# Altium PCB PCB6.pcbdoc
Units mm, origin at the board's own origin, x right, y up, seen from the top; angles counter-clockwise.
Board outline 112.7 x 112.94 mm, 2 copper layers (Top Layer, Bottom Layer); 46 components, 40 nets, 167 pads, 45 vias.
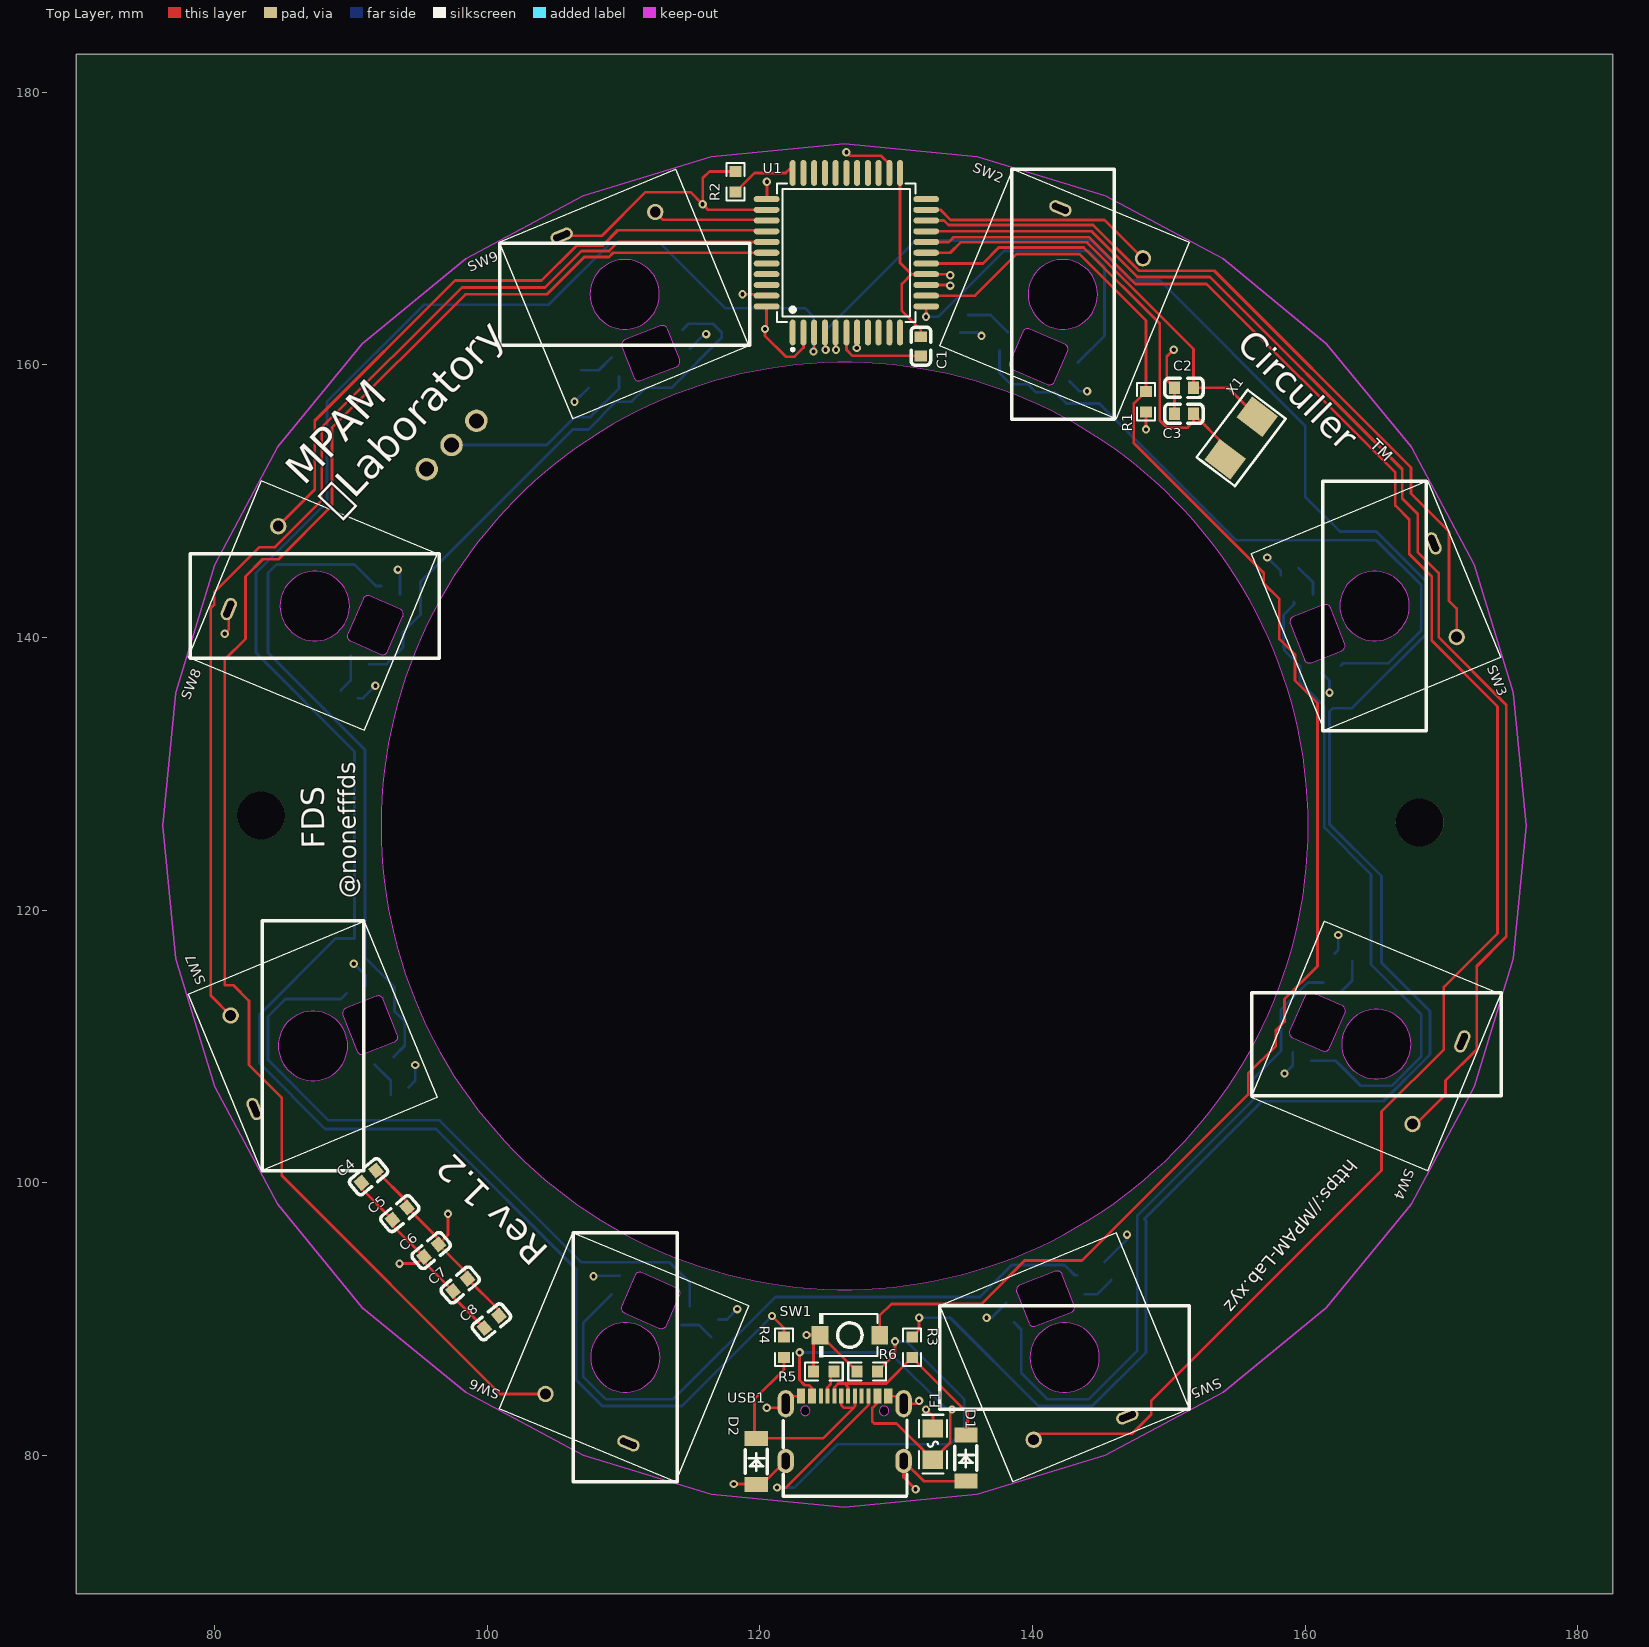
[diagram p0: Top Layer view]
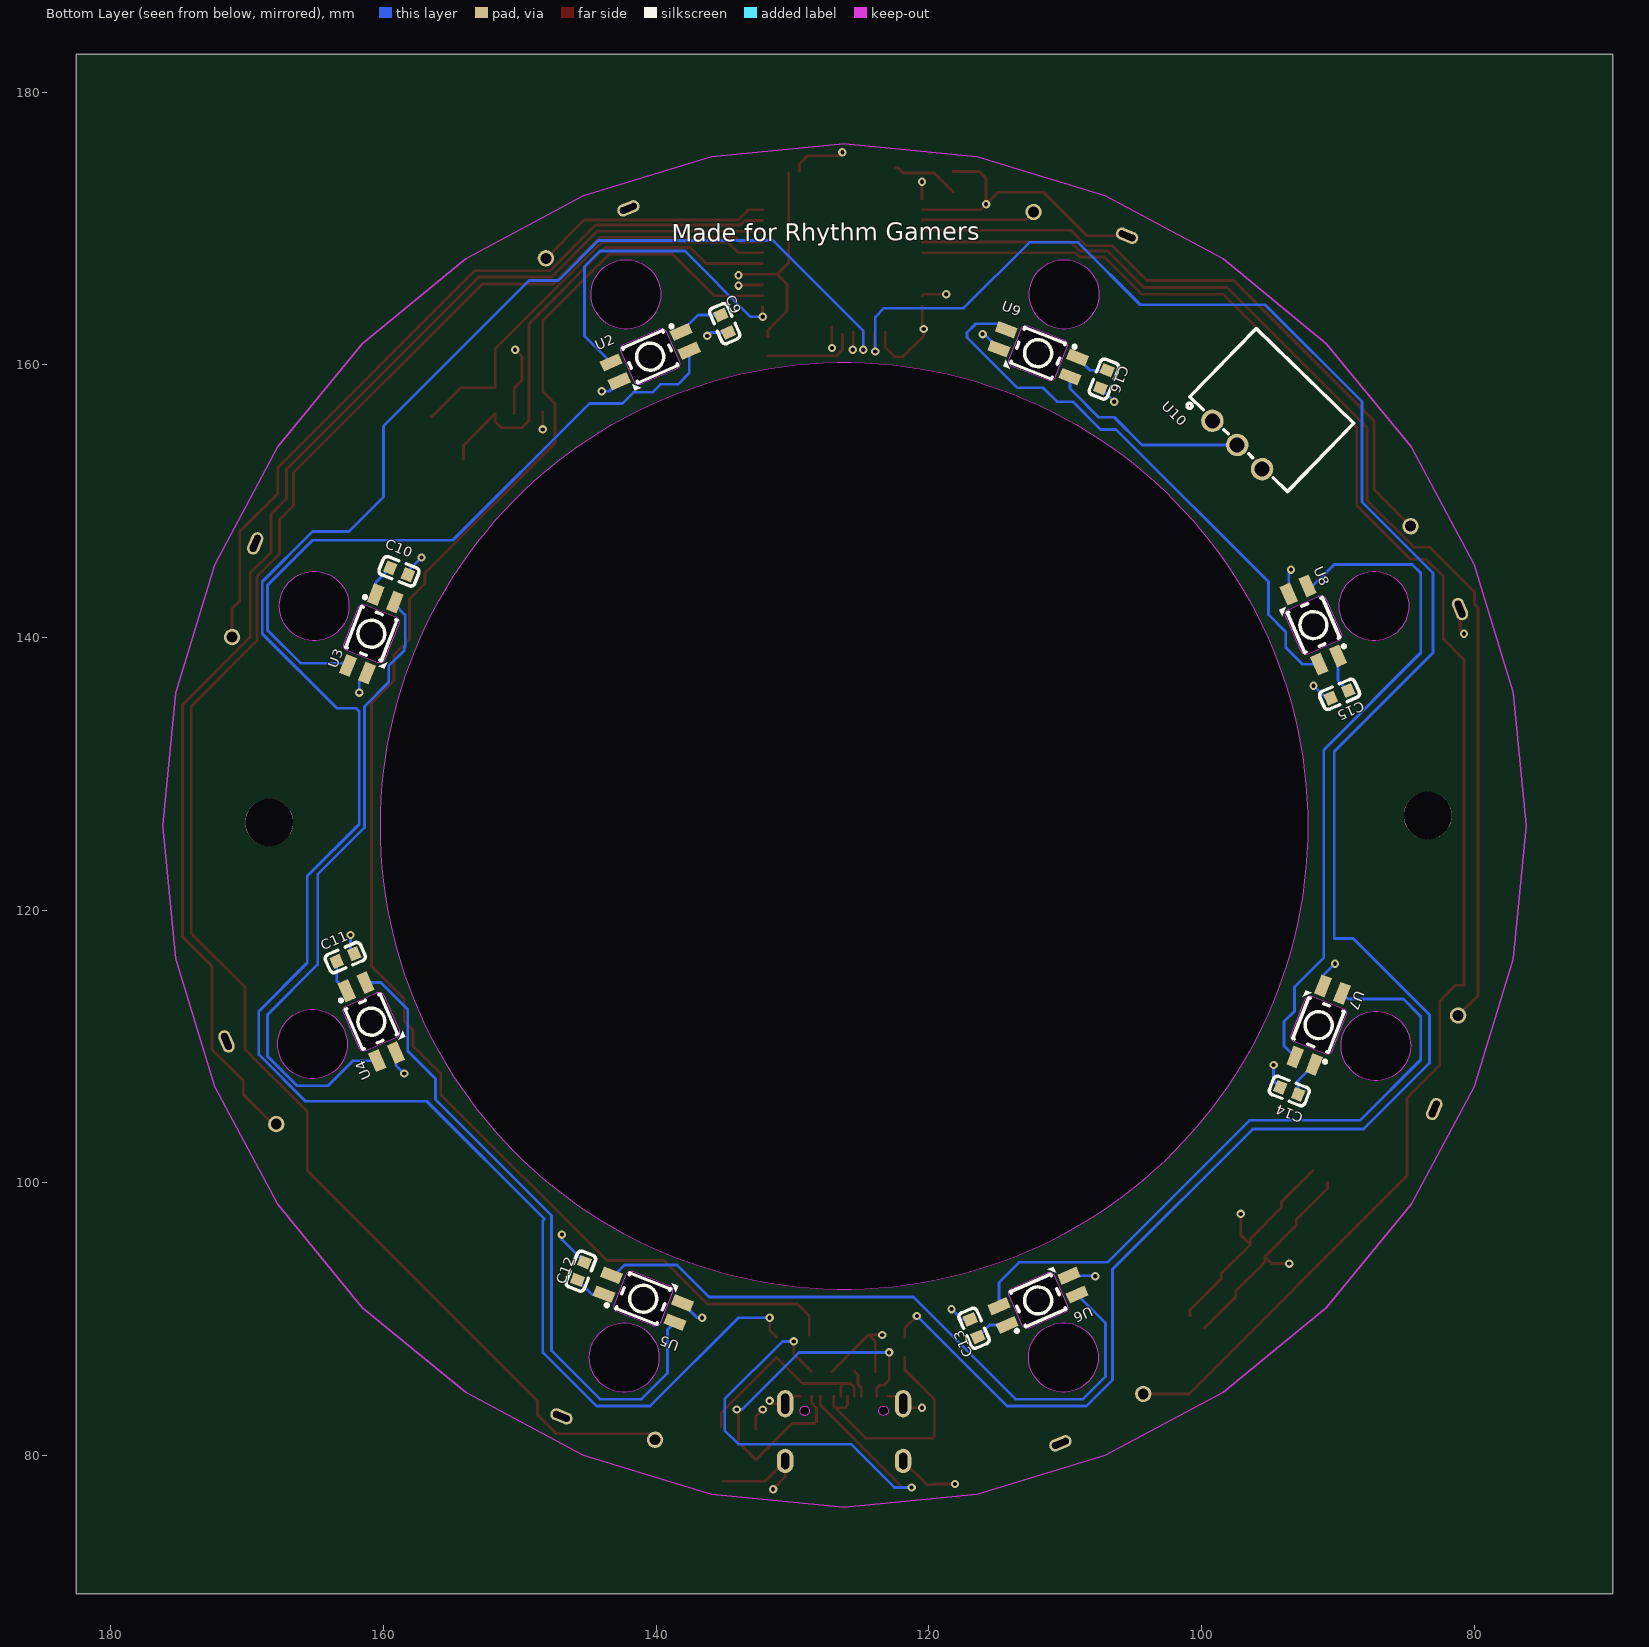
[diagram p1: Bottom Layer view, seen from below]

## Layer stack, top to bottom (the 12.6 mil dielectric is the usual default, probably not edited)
Top Layer: signal copper (thickness not stored)
Dielectric: dielectric 0.32, FR-4, Dk 4.8
Bottom Layer: signal copper (thickness not stored)

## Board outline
182.55,69.85 69.85,69.85 69.85,182.785 182.55,182.785
cut-out: 160.219,126.175 ccw(c126.219,126.175) 92.219,126.175 ccw(c126.219,126.175)

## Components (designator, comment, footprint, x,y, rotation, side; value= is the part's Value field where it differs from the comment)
C1 "CL10A105KB8NNNC" C0603 131.807,161.354 r270 top
C2 "CL10C220JB8NNNC" C0603 151.111,158.306 r0 top
C3 "CL10C220JB8NNNC" C0603 151.111,156.401 r0 top
C4 "CC0603KRX7R9BB104" C0603 91.309,100.454 r40.26 top
C5 "CC0603KRX7R9BB104" C0603 93.603,97.745 r40.26 top
C6 "CC0603KRX7R9BB104" C0603 95.897,95.037 r40.26 top
C7 "CC0603KRX7R9BB104" C0603 98.031,92.517 r40.26 top
C8 "CL10B474KA8NNNC" C0603 100.325,89.809 r40.26 top
C9 "CC0603KRX7R9BB104" C0603 134.982,163.005 r246.46 bottom
C10 "CC0603KRX7R9BB104" C0603 158.858,144.844 r201.46 bottom
C11 "CC0603KRX7R9BB104" C0603 162.795,116.523 r156.38 bottom
C12 "CC0603KRX7R9BB104" C0603 145.523,93.536 r111.38 bottom
C13 "CC0603KRX7R9BB104" C0603 116.694,89.345 r66.46 bottom
C14 "CC0603KRX7R9BB104" C0603 93.58,106.744 r21.46 bottom
C15 "CC0603KRX7R9BB104" C0603 89.897,135.827 r336.38 bottom
C16 "CC0603KRX7R9BB104" C0603 107.169,158.941 r291.38 bottom
D1 "ZMM3V6" LL-34_L3.5-W1.5-RD 135.109,79.82 r270 top
D2 "ZMM3V6" LL-34_L3.5-W1.5-RD 119.742,79.566 r270 top
F1 "2.5A/32VFUSESMD0805" F0805 132.696,80.836 r270 top
R1 "0603WAF1002T5E" R0603 148.317,157.29 r90 top
R2 "0603WAF1002T5E" R0603 118.218,173.419 r90 top
R3 "0603WAF220JT5E" R0603 131.172,87.948 r270 top
R4 "0603WAF220JT5E" R0603 121.774,87.948 r270 top
R5 "0603WAF5101T5E" R0603 124.695,86.17 r0 top
R6 "0603WAF5101T5E" R0603 127.87,86.17 r0 top
SW1 "TS-1088-AR02016" SW-SMD_L3.9-W3.0-P4.45 126.6,88.837 r180 top
SW2 "佳达隆矮轴_焊接" 佳达隆矮轴焊接#1 142.221,165.164 r337.31 top
SW3 "佳达隆矮轴_焊接" 佳达隆矮轴焊接#2 165.081,142.304 r292.39 top
SW4 "佳达隆矮轴_焊接" 佳达隆矮轴焊接#3 165.208,110.173 r247.48 top
SW5 "佳达隆矮轴_焊接" 佳达隆矮轴焊接#4 142.348,87.186 r202.51 top
SW6 "佳达隆矮轴_焊接" 佳达隆矮轴焊接#1 110.136,87.203 r157.7 top
SW7 "佳达隆矮轴_焊接" 佳达隆矮轴焊接#2 87.23,110.046 r112.88 top
SW8 "佳达隆矮轴_焊接" 佳达隆矮轴焊接#2 87.357,142.304 r67.7 top
SW9 "佳达隆矮轴_焊接" 佳达隆矮轴焊接#1 110.09,165.164 r22.79 top
U1 "ATMEGA32U4-AU" QFP-44_L10.0-W10.0-P0.80-LS13.2-BL 126.346,168.212 r0 top
U2 "WS2812B-3528幻彩反贴" LED-SMD_L3.2-W2.8-TR 140.443,160.592 r156.46 bottom
U3 "WS2812B-3528幻彩反贴" LED-SMD_L3.2-W2.8-TR 160.89,140.272 r111.46 bottom
U4 "WS2812B-3528幻彩反贴" LED-SMD_L3.2-W2.8-TR 160.89,111.824 r66.38 bottom
U5 "WS2812B-3528幻彩反贴" LED-SMD_L3.2-W2.8-TR 140.951,91.504 r21.38 bottom
U6 "WS2812B-3528幻彩反贴" LED-SMD_L3.2-W2.8-TR 111.995,91.377 r336.46 bottom
U7 "WS2812B-3528幻彩反贴" LED-SMD_L3.2-W2.8-TR 91.421,111.57 r291.46 bottom
U8 "WS2812B-3528幻彩反贴" LED-SMD_L3.2-W2.8-TR 91.802,140.907 r246.38 bottom
U9 "WS2812B-3528幻彩反贴" LED-SMD_L3.2-W2.8-TR 111.995,160.846 r201.38 bottom
U10 "XH2.54-WI-3P" CONN-TH_XH2.54-WI-3P 97.39,154.115 r224.2 bottom
USB1 "TYPE-C 16PIN 2MD(073)" USB-C-SMD_TYPE-C-6PIN-2MD-073 126.219,81.979 r0 top
X1 "XSHEELNANF-16MHZ" OSC-SMD_2P-L5.0-W3.2 155.302,154.623 r52.91 top

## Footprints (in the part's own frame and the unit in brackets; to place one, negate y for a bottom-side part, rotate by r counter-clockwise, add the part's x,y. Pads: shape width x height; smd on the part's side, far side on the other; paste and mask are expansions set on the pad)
C0603 [mm]
  rect 0.8x0.9 smd: 1(-0.7,0) 2(0.7,0)
  silkscreen extent -1.41,-0.71 1.39,0.72
CONN-TH_XH2.54-WI-3P [mm]
  round 1.65 hole 1.1: 1(-2.54,0) 2(0,0) 3(2.54,0)
  silkscreen extent -4.96,-0.56 5.02,7.09
F0805 [mm]
  rect 1.335x1.5 smd: 1(-1.142,0) 2(1.142,0)
  silkscreen extent -2.16,-1.02 2.16,1.02
LED-SMD_L3.2-W2.8-TR [mm]
  rect 1.5x0.82 smd: 1(2.8,0.75) 2(2.8,-0.75) 3(-2.8,-0.75) 4(-2.8,0.75)
  Multi-Layer board cut-out: 1.8,-1.2 1.746,-1.4 1.6,-1.547 1.4,-1.6 1.4,-1.6 1.4,-1.6 -1.4,-1.6 -1.403,-1.6 -1.406,-1.6 -1.406,-1.6 -1.604,-1.545 -1.747,-1.398 -1.8,-1.2 -1.8,-1.2 -1.8,-1.2 -1.8,-1.2 -1.8,-1.2 -1.8,-1.2 -1.8,1.2 -1.746,1.4 -1.6,1.546 -1.4,1.6 -1.4,1.6 1.4,1.6 1.4,1.6 1.6,1.547 1.746,1.4 1.8,1.2 1.8,1.2
  Multi-Layer keep-out region: 1.8,-1.2 1.746,-1.4 1.6,-1.547 1.4,-1.6 1.4,-1.6 1.4,-1.6 -1.4,-1.6 -1.403,-1.6 -1.406,-1.6 -1.406,-1.6 -1.604,-1.545 -1.747,-1.398 -1.8,-1.2 -1.8,-1.2 -1.8,-1.2 -1.8,-1.2 -1.8,-1.2 -1.8,-1.2 -1.8,1.2 -1.746,1.4 -1.6,1.546 -1.4,1.6 -1.4,1.6 1.4,1.6 1.4,1.6 1.6,1.547 1.746,1.4 1.8,1.2 1.8,1.2
  silkscreen extent -2.03,-1.83 2.42,1.52
LL-34_L3.5-W1.5-RD [mm]
  rect 1.1x1.7 smd: 1(-1.7,0) 2(1.7,0)
  silkscreen extent -0.9,-0.8 0.9,0.8
OSC-SMD_2P-L5.0-W3.2 [mm]
  rect 1.9x2.4 smd: 1(-1.95,0) 2(1.95,0)
  silkscreen extent -3.1,-1.75 3.1,1.75
QFP-44_L10.0-W10.0-P0.80-LS13.2-BL [mil]
  oval 17.36x74.62 smd: 1(-155,-230.37) 2(-124,-230.37) 3(-93,-230.37) 4(-62,-230.37) 5(-31,-230.37) 6(0,-230.37) 7(31,-230.37) 8(62,-230.37) 9(93,-230.37) 10(124,-230.37) 11(155,-230.37) 23(155,230.37) 24(124,230.37) 25(93,230.37) 26(62,230.37) 27(31,230.37) 28(0,230.37) 29(-31,230.37) 30(-62,230.37) 31(-93,230.37) 32(-124,230.37) 33(-155,230.37)
  oval 74.62x17.36 smd: 12(230.37,-155) 13(230.37,-124) 14(230.37,-93) 15(230.37,-62) 16(230.37,-31) 17(230.37,0) 18(230.37,31) 19(230.37,62) 20(230.37,93) 21(230.37,124) 22(230.37,155) 34(-230.37,155) 35(-230.37,124) 36(-230.37,93) 37(-230.37,62) 38(-230.37,31) 39(-230.37,0) 40(-230.37,-31) 41(-230.37,-62) 42(-230.37,-93) 43(-230.37,-124) 44(-230.37,-155)
  silkscreen extent -200,-283 200,200
R0603 [mm]
  rect 0.806x0.864 smd: 1(-0.753,0) 2(0.753,0)
  silkscreen extent -1.39,-0.66 1.39,0.66
SW-SMD_L3.9-W3.0-P4.45 [mm]
  rect 1.23x1.36 smd: 1(-2.185,0) 2(2.185,0)
  silkscreen extent -2.03,-1.62 2.25,1.62
USB-C-SMD_TYPE-C-6PIN-2MD-073 [mm]
  rect 0.6x1.1 smd: 1(-3.2,2.375) 2(-2.4,2.375) 11(2.4,2.375) 12(3.2,2.375)
  rect 0.3x1.1 smd: 3(-1.75,2.375) 4(-1.25,2.375) 5(-0.75,2.375) 6(-0.25,2.375) 7(0.25,2.375) 8(0.75,2.375) 9(1.25,2.375) 10(1.75,2.375)
  oval 1.2x1.8 hole 0.6 slot 1.2 at 90 deg: 13(-4.325,-2.375) 14(4.325,-2.375)
  oval 1.2x2 hole 0.6 slot 1.5 at 90 deg: 13(-4.325,1.825) 14(4.325,1.825)
  Multi-Layer board cut-out: -2.54,1.305 -2.575,1.457 -2.672,1.579 -2.812,1.646 -2.968,1.646 -3.108,1.579 -3.205,1.457 -3.24,1.305 -3.24,1.305 -3.205,1.153 -3.108,1.031 -2.968,0.964 -2.812,0.964 -2.672,1.031 -2.575,1.153 -2.54,1.305
  Multi-Layer board cut-out: 3.24,1.305 3.205,1.457 3.108,1.579 2.968,1.646 2.812,1.646 2.672,1.579 2.575,1.457 2.54,1.305 2.54,1.305 2.575,1.153 2.672,1.031 2.812,0.964 2.968,0.964 3.108,1.031 3.205,1.153 3.24,1.305
  Multi-Layer keep-out region: -2.54,1.305 -2.575,1.457 -2.672,1.579 -2.812,1.646 -2.968,1.646 -3.108,1.579 -3.205,1.457 -3.24,1.305 -3.24,1.305 -3.205,1.153 -3.108,1.031 -2.968,0.964 -2.812,0.964 -2.672,1.031 -2.575,1.153 -2.54,1.305
  Multi-Layer keep-out region: 3.24,1.305 3.205,1.457 3.108,1.579 2.968,1.646 2.812,1.646 2.672,1.579 2.575,1.457 2.54,1.305 2.54,1.305 2.575,1.153 2.672,1.031 2.812,0.964 2.968,0.964 3.108,1.031 3.205,1.153 3.24,1.305
  silkscreen extent -4.5,-4.97 4.57,0.6
佳达隆矮轴焊接#1 [mm]
  oval 1.7x0.9 hole 0.5 slot 1.3 at 0 deg: 1(-2.6,5.75)
  round 1.2 hole 0.8: 2(4.4,4.7)
  Multi-Layer board cut-out: 2.353,0.984 1.693,1.907 0.698,2.453 -0.436,2.513 -1.483,2.075 -2.236,1.226 -2.546,0.134 -2.353,-0.984 -2.353,-0.984 -1.693,-1.907 -0.698,-2.453 0.436,-2.513 1.483,-2.075 2.236,-1.226 2.546,-0.134 2.353,0.984
  Multi-Layer keep-out region: 2.353,0.984 1.693,1.907 0.698,2.453 -0.436,2.513 -1.483,2.075 -2.236,1.226 -2.546,0.134 -2.353,-0.984 -2.353,-0.984 -1.693,-1.907 -0.698,-2.453 0.436,-2.513 1.483,-2.075 2.236,-1.226 2.546,-0.134 2.353,0.984
  silkscreen extent -7,-9.9 7,9.9
佳达隆矮轴焊接#2 [mm]
  oval 1.7x0.9 hole 0.5 slot 1.3 at 0 deg: 1(-2.6,5.75)
  round 1.2 hole 0.8: 2(4.4,4.7)
  Multi-Layer board cut-out: 0.971,2.358 -0.148,2.546 -1.238,2.229 -2.083,1.471 -2.515,0.422 -2.449,-0.711 -1.898,-1.703 -0.971,-2.358 -0.971,-2.358 0.148,-2.546 1.238,-2.229 2.083,-1.471 2.515,-0.422 2.449,0.711 1.898,1.703 0.971,2.358
  Multi-Layer keep-out region: 0.971,2.358 -0.148,2.546 -1.238,2.229 -2.083,1.471 -2.515,0.422 -2.449,-0.711 -1.898,-1.703 -0.971,-2.358 -0.971,-2.358 0.148,-2.546 1.238,-2.229 2.083,-1.471 2.515,-0.422 2.449,0.711 1.898,1.703 0.971,2.358
  silkscreen extent -9.9,-7 9.9,7
佳达隆矮轴焊接#3 [mm]
  oval 1.7x0.9 hole 0.5 slot 1.3 at 180 deg: 1(-2.6,5.75)
  round 1.2 hole 0.8: 2(4.4,4.7)
  Multi-Layer board cut-out: -0.977,2.356 -1.902,1.699 -2.451,0.705 -2.514,-0.428 -2.079,-1.476 -1.233,-2.232 -0.142,-2.546 0.977,-2.356 0.977,-2.356 1.902,-1.699 2.451,-0.705 2.514,0.428 2.079,1.476 1.233,2.232 0.142,2.546 -0.977,2.356
  Multi-Layer keep-out region: -0.977,2.356 -1.902,1.699 -2.451,0.705 -2.514,-0.428 -2.079,-1.476 -1.233,-2.232 -0.142,-2.546 0.977,-2.356 0.977,-2.356 1.902,-1.699 2.451,-0.705 2.514,0.428 2.079,1.476 1.233,2.232 0.142,2.546 -0.977,2.356
  silkscreen extent -7,-9.9 7,9.9
佳达隆矮轴焊接#4 [mm]
  oval 1.7x0.9 hole 0.5 slot 1.3 at 180 deg: 1(-2.6,5.75)
  round 1.2 hole 0.8: 2(4.4,4.7)
  Multi-Layer board cut-out: -2.356,0.976 -2.546,-0.142 -2.232,-1.233 -1.476,-2.079 -0.428,-2.514 0.705,-2.451 1.699,-1.902 2.356,-0.976 2.356,-0.976 2.546,0.142 2.232,1.233 1.476,2.079 0.428,2.514 -0.705,2.451 -1.699,1.902 -2.356,0.976
  Multi-Layer keep-out region: -2.356,0.976 -2.546,-0.142 -2.232,-1.233 -1.476,-2.079 -0.428,-2.514 0.705,-2.451 1.699,-1.902 2.356,-0.976 2.356,-0.976 2.546,0.142 2.232,1.233 1.476,2.079 0.428,2.514 -0.705,2.451 -1.699,1.902 -2.356,0.976
  silkscreen extent -9.9,-7 9.9,7

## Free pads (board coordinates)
  round 3.5 hole 3.5 unplated: 13(83.42,126.937)
  round 3.5 hole 3.5: 14(168.383,126.429)

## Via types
v1: diameter 0.61, hole 0.305, Top Layer to Bottom Layer, 45 vias

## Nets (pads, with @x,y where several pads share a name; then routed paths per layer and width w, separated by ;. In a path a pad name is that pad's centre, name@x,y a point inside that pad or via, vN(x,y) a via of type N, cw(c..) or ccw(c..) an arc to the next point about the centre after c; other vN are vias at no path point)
1: SW9.2 U1.36 | length 8.4
  Top Layer w0.203: SW9.2 112.903,170.625 120.444,170.625 U1.36
2: SW5.2 U1.18 | length 133.8
  Top Layer w0.203: U1.18 133.865,168.999 134.22,169.355 144.126,169.355 147.555,165.926 152.762,165.926 166.605,152.083 166.605,149.67 167.621,148.654 167.621,146.114 169.272,144.463 169.272,139.764 174.098,134.938 174.098,118.301 170.161,114.364 170.161,109.792 165.589,105.22 165.589,100.902 148.698,84.011 148.698,82.995 147.301,81.598 140.522,81.598 SW5.2
3: SW2.2 U1.21 | length 17.4
  Top Layer w0.203: U1.21 133.247,171.361 133.995,170.613 145.283,170.613 SW2.2
4: SW6.2 U1.39 | length 124
  Top Layer w0.203: SW6.2 100.941,84.524 84.944,100.521 84.944,106.236 82.531,108.649 82.531,113.348 81.388,114.491 80.753,114.491 80.753,138.367 82.277,139.891 82.277,144.463 83.547,145.733 84.69,145.733 88.627,149.67 88.627,155.385 98.406,165.164 104.375,165.164 107.118,167.907 108.947,167.907 109.252,168.212 U1.39
5: SW3.2 U1.20 | length 56.9
  Top Layer w0.203: U1.20 133.509,170.574 133.839,170.244 144.445,170.244 147.798,166.891 153.321,166.891 167.748,152.464 167.748,150.559 170.542,147.765 170.542,142.685 171.103,142.124 SW3.2
6: SW7.2 U1.38 | length 86
  Top Layer w0.203: SW7.2 79.737,113.724 79.737,142.177 79.991,142.431 79.991,143.32 83.293,146.622 84.436,146.622 87.865,150.051 87.865,155.385 98.152,165.672 104.248,165.672 106.915,168.339 108.947,168.339 109.608,168.999 U1.38
7: SW4.2 U1.19 | length 96.3
  Top Layer w0.203: U1.19 144.329,169.787 147.682,166.434 153.016,166.434 167.113,152.337 167.113,150.178 168.256,149.035 168.256,146.241 169.78,144.717 169.78,140.018 174.733,135.065 174.733,118.047 172.574,115.888 172.574,109.792 170.288,107.506 170.288,106.49 168.107,104.308 SW4.2
8: SW8.2 U1.37 | length 47.8
  Top Layer w0.203: SW8.2 87.357,150.837 87.357,155.893 97.644,166.18 103.994,166.18 106.534,168.72 108.439,168.72 109.582,169.863 120.419,169.863 U1.37
$1N992: C2.2 U1.17 X1.2 | length 31.6
  Top Layer w0.203: U1.17 133.966,168.212 134.728,168.974 143.999,168.974 151.811,161.162 C2.2 154.351,158.306 X1.2
$1N1040: C3.2 U1.16 X1.1 | length 34.8
  Top Layer w0.203: U1.16 136.354,167.424 137.522,168.593 143.745,168.593 149.333,163.005 149.333,155.893 149.841,155.385 151.365,155.385 151.811,155.831 C3.2 154.126,154.086 X1.1
$1N1214: R1.2 SW1.1 U1.13 | length 119.4
  Top Layer w0.203: SW1.1 128.785,90.26 129.648,91.123 136.252,91.123 139.427,94.298 143.618,94.298 155.81,106.49 155.81,108.014 157.842,110.046 157.842,111.189 158.477,111.824 158.477,113.475 160.89,115.888 160.89,135.192 159.239,136.843 159.239,138.748 158.096,139.891 158.096,142.812 156.953,143.955 156.953,144.717 147.428,154.242 147.428,157.154 R1.2 148.317,163.241 143.444,168.115 138.822,168.115 135.77,165.062 U1.13
$1N1318: R2.1 U1.33 | length 4.9
  Top Layer w0.203: R2.1 119.607,174.054 121.892,174.054 122.282,174.444 U1.33@122.409,174.444
$1N2823: F1.2 USB1.2 USB1.11 | length 28.6
  Top Layer w0.203: v1(122.917,87.567) 122.917,85.535 123.294,85.158 123.616,85.158 123.819,84.955 USB1.2 ; USB1.11 128.619,83.871 128.251,83.503 128.251,82.487 128.378,82.36 130.03,82.36 F1.2 133.966,80.963 133.966,83.249 v1(134.093,83.376)
  Bottom Layer w0.203: v1(122.917,87.567) 129.521,87.567 133.712,83.376 v1(134.093,83.376)
$1N3423: D1.1 R3.2 USB1.5 USB1.7 | length 15.1
  Top Layer w0.203: USB1.5 125.469,85.005 125.745,85.281 126.219,85.281 ; USB1.7 126.473,84.358 126.473,85.027 126.219,85.281 ; 135.236,82.106 135.236,83.13 R3.2 129.267,85.289 129.267,85.281 126.219,85.281
$1N3438: D2.1 R4.2 USB1.6 USB1.8 | length 17.4
  Top Layer w0.203: R4.2 121.774,86.297 119.615,84.138 119.615,81.393 D2.1 124.617,81.266 126.854,83.503 ; USB1.6 125.969,83.702 126.169,83.503 126.854,83.503 ; USB1.8 126.981,84.342 126.981,83.63 126.854,83.503
$1N3472: R5.2 USB1.4 | length 2
  Top Layer w0.203: USB1.4 124.969,85.005 125.195,85.23 125.195,85.916 R5.2
$1N3479: R6.2 USB1.10 | length 37
  Top Layer w0.203: v1@121.393,77.661 121.928,77.661 127.969,83.702 USB1.10 ; R6.2 129.914,87.46 v1(129.914,88.374)
  Bottom Layer w0.203: v1(121.266,77.661) 122.536,77.661 125.711,80.836 133.966,80.836 134.982,81.852 134.982,84.138 130.746,88.374 v1(129.914,88.374)
$1N3933: U2.2 U3.4 | length 49.3
  Bottom Layer w0.203: U2.2 137.577,159.394 138.411,158.56 139.681,158.56 140.265,157.976 141.662,157.976 142.475,157.163 144.888,157.163 154.921,147.13 165.208,147.13 168.51,143.828 168.51,140.526 166.097,138.113 162.785,138.113 U3.4
$1N3938: U3.2 U4.4 | length 47.5
  Bottom Layer w0.203: U3.2 159.168,142.411 158.41,141.654 158.41,139.322 158.477,139.256 158.477,139.053 159.62,137.91 159.62,136.716 161.398,134.938 161.398,126.048 164.827,122.619 164.827,116.015 168.51,112.332 168.51,109.284 166.351,107.125 164.065,107.125 162.232,108.958 U4.4
$1N3943: U4.2 U5.4 | length 48
  Bottom Layer w0.203: U5.4 139.173,89.229 139.173,86.043 141.078,84.138 144.126,84.138 147.682,87.694 147.682,97.6 156.191,106.109 156.191,107.633 158.223,109.665 158.223,112.713 160.2,114.69 U4.2
$1N3948: U5.2 U6.4 | length 48.2
  Bottom Layer w0.203: U6.4 107.042,89.721 107.042,85.789 108.693,84.138 113.646,84.138 121.139,91.631 136.125,91.631 138.474,93.98 142.336,93.98 143.092,93.223 U5.2
$1N3953: U6.2 U7.4 | length 49.1
  Bottom Layer w0.203: U7.4 89.272,113.475 85.198,113.475 83.928,112.205 83.928,109.03 88.373,104.585 96.501,104.585 106.915,94.171 113.392,94.171 114.862,92.701 U6.2
$1N3959: U7.2 U8.4 | length 49.2
  Bottom Layer w0.203: U8.4 91.857,143.773 90.278,145.352 84.563,145.352 83.928,144.717 83.928,138.875 91.04,131.763 91.04,116.523 93.199,114.364 93.199,112.586 93.961,111.824 93.961,110.056 U7.2
$1N3965: U8.2 U9.4 | length 41.5
  Bottom Layer w0.203: U8.2 92.619,138.041 93.834,139.256 93.834,140.399 95.104,141.669 95.104,144.082 106.28,155.258 107.423,155.258 109.455,157.29 110.598,157.29 111.614,158.306 113.519,158.306 117.202,161.989 117.202,162.37 116.567,163.005 114.769,163.005 U9.4
$1N4279: C9.1 U2.1 | length 3.4
  Bottom Layer w0.203: C9.1 136.927,163.646 U2.1
$1N4296: C10.1 U3.1 | length 2.4
  Bottom Layer w0.203: C10.1 160.564,144.045 U3.1
$1N4306: C11.1 U4.1 | length 2.5
  Bottom Layer w0.203: U4.1 163.437,114.826 C11.1
$1N4316: C12.1 U5.1 | length 2.4
  Bottom Layer w0.203: U5.1 144.721,91.826 C12.1
$1N4320: C13.1 U6.1 | length 2.5
  Bottom Layer w0.203: U6.1 115.547,89.571 C13.1
$1N4353: C16.1 U9.1 | length 2.6
  Bottom Layer w0.203: C16.1 108.184,159.593 U9.1
$1N4416: C14.1 U7.1 | length 2.7
  Bottom Layer w0.203: U7.1 92.929,107.508 C14.1
$1N4551: C15.1 U8.1 | length 2.8
  Bottom Layer w0.203: C15.1 89.993,136.844 U8.1
$1N4867: C1.2 U1.6 | length 6.8
  Top Layer w0.203: U1.6@126.346,162.233 126.346,161.1 126.792,160.654 C1.2
D+: R4.1 U1.3 | length 161.5
  Top Layer w0.203: v1(120.885,90.234) 121.774,89.345 R4.1 ; v1(123.933,160.973) 123.984,161.024 U1.3
  Bottom Layer w0.203: v1(120.885,90.234) 114.281,83.63 108.439,83.63 106.534,85.535 106.534,93.663 96.247,103.95 88.119,103.95 83.293,108.776 83.293,112.332 88.881,117.92 90.278,117.92 90.278,131.636 83.039,138.875 83.039,144.717 88.246,149.924 88.246,157.29 95.358,164.402 104.502,164.402 109.074,168.974 112.63,168.974 117.456,164.148 123.298,164.148 123.933,163.513 v1(123.933,160.973)
D-: R3.1 U1.4 | length 162.7
  Top Layer w0.203: U1.4 124.822,162.31 v1@124.822,161.1 ; R3.1 131.68,89.209 v1(131.68,90.107)
  Bottom Layer w0.203: v1(124.822,161.1) 124.822,162.497 131.426,169.101 144.253,169.101 147.174,166.18 149.333,166.18 160.001,155.512 160.001,150.305 162.541,147.765 165.208,147.765 168.891,144.082 168.891,140.272 163.43,134.811 162.033,134.811 161.779,134.557 161.779,126.302 165.589,122.492 165.589,116.142 169.145,112.586 169.145,109.411 165.716,105.982 156.826,105.982 148.19,97.346 148.317,97.219 148.317,87.567 144.38,83.63 140.443,83.63 133.966,90.107 v1(131.68,90.107)
DOUT: U9.2 U10.2 | length 14.9
  Bottom Layer w0.203: U10.2 104.375,154.115 106.407,156.147 107.55,156.147 109.661,158.258 U9.2
GND: C1.1 C2.1 C3.1 C4.1 C5.1 C6.1 C7.1 C8.1 D1.2 D2.2 R2.2 R5.1 R6.1 SW1.2 SW2.1 SW3.1 SW4.1 SW5.1 SW6.1 SW7.1 SW8.1 SW9.1 U1.5 U1.15 U1.23 U1.35 U1.43 U2.3 U3.3 U4.3 U5.3 U6.3 U7.3 U8.3 U9.3 U10.1 USB1.1 USB1.12 USB1.13 USB1.14 | length 103.7
  Top Layer w0.203: v1(80.753,140.272) 81.051,140.569 SW8.1 ; C4.1 90.775,99.587 C5.1 93.069,96.878 C6.1 ; v1(93.574,94.077) 94.856,94.077 C6.1 ; C8.1 97.497,91.65 C7.1 95.363,94.199 C6.1 ; SW9.1 108.415,169.458 111.614,172.657 114.916,172.657 v1(115.805,171.768) ; v1(118.091,77.915) 119.693,77.915 D2.2 120.156,77.866 USB1.13@121.894,79.604 ; R2.2 116.305,174.172 115.805,173.673 v1(115.805,171.768) ; v1(118.733,165.164) 120.393,165.164 U1.43 ; U1.35 116.212,171.361 v1(115.805,171.768) ; v1(120.504,83.503) 121.593,83.503 121.894,83.804 122.444,84.354 USB1.1 ; v1(123.425,88.837) SW1.2 ; R5.1 123.933,86.178 123.933,88.355 SW1.2 ; U1.5 125.559,161.125 v1(125.584,161.1) ; R6.1 124.45,88.837 SW1.2 ; USB1.12 129.994,84.354 130.544,83.804 131.473,83.804 v1(131.68,84.011) ; U1.23 130.283,167.475 131.121,166.637 ; v1(131.426,77.534) 130.544,78.416 130.544,79.604 132.028,78.12 D1.2 ; C1.1 131.807,162.555 130.41,163.952 130.41,165.926 131.121,166.637 ; v1(133.966,166.561) 133.89,166.637 U1.15 131.121,166.637 ; v1(150.349,161.1) 149.841,160.592 149.841,158.876 C2.1 C3.1
  Bottom Layer w0.203: v1(90.215,116.073) 91.095,115.193 U7.3 ; v1(93.453,144.971) 93.611,144.812 U8.3 ; v1(107.804,93.155) 107.832,93.183 U6.3 ; U9.3 115.951,162.243 v1(116.059,162.243) ; v1(136.633,90.107) 136.996,90.107 U5.3 ; U2.3 143.445,158.052 v1(143.999,158.052) ; v1(158.477,108.014) 159.081,108.617 U4.3 ; U3.3 161.779,136.828 v1(161.779,135.954)
LED: U1.12 U2.4 | length 24.2
  Top Layer w0.203: v1(132.188,163.513) 132.198,163.522 U1.12
  Bottom Layer w0.203: v1(132.188,163.513) 133.077,163.513 137.903,168.339 144.126,168.339 145.269,167.196 145.269,162.12 U2.4
VCC: C4.2 C5.2 C6.2 C7.2 C8.2 C9.2 C10.2 C11.2 C12.2 C13.2 C14.2 C15.2 C16.2 F1.1 R1.1 U1.2 U1.7 U1.14 U1.24 U1.34 U1.44 U10.3 | length 49.6
  Top Layer w0.203: C4.2 94.137,98.612 C5.2 96.431,95.904 C6.2 ; v1(97.136,97.727) 97.136,96.194 C6.2 ; C8.2 100.859,90.676 C7.2 98.565,93.355 C6.2 ; U1.44 120.495,162.741 v1(120.377,162.624) 120.377,162.116 121.901,160.592 122.536,160.592 123.197,161.252 U1.2 ; U1.34 120.514,172.168 v1(120.514,173.419) ; v1(126.346,175.578) 126.6,175.324 128.886,175.324 129.496,174.714 U1.24@129.496,174.19 ; v1(127.108,161.227) 127.134,161.252 U1.7@127.134,162.741 ; v1(132.188,83.376) 132.696,82.868 F1.1 ; U1.14 133.915,165.85 v1(133.966,165.799) ; v1(148.317,155.258) R1.1
  Bottom Layer w0.203: C15.2 90.887,135.546 v1(91.802,136.462) ; C14.2 94.723,107.491 v1(94.723,108.649) ; v1(106.407,157.29) 106.425,157.29 C16.2 ; C13.2 117.59,89.986 v1(118.345,90.742) ; C9.2 136.005,162.363 v1(136.252,162.116) ; C12.2 146.92,95.84 v1(146.92,96.203) ; v1(157.207,145.86) 158.207,144.86 C10.2 ; C11.2 162.414,117.064 v1(162.414,118.174)
"": pad.13 pad.14 U1.1 U1.8 U1.9 U1.10 U1.11 U1.22 U1.25 U1.26 U1.27 U1.28 U1.29 U1.30 U1.31 U1.32 U1.40 U1.41 U1.42 USB1.3 USB1.9

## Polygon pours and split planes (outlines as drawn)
GND on GND (split plane): 126.2,76.458 116.496,77.414 107.164,80.244 98.565,84.841 91.027,91.027 84.841,98.565 80.244,107.164 77.414,116.496 76.458,126.2 77.414,135.904 80.244,145.235 84.841,153.835 91.027,161.373 98.565,167.559 107.164,172.156 116.496,174.986 125.895,175.912 ccw(c129.451,174.553) 125.785,175.578 ccw(c126.065,175.297) 126.346,175.016 ccw(c126.627,175.297) 126.908,175.578 ccw(c127.375,175.879) 126.819,175.881 135.904,174.986 145.235,172.156 153.835,167.559 161.373,161.373 167.559,153.835 172.156,145.235 174.986,135.904 175.942,126.2 174.986,116.496 172.156,107.164 167.559,98.565 161.373,91.027 153.835,84.841 145.235,80.244 135.904,77.414
VCC on VCC (split plane): 126.2,76.458 116.496,77.414 107.164,80.244 98.565,84.841 91.027,91.027 84.841,98.565 80.244,107.164 77.414,116.496 76.458,126.2 77.414,135.904 80.244,145.235 84.841,153.835 91.027,161.373 98.565,167.559 107.164,172.156 116.496,174.986 126.2,175.942 135.904,174.986 145.235,172.156 153.835,167.559 161.373,161.373 167.559,153.835 172.156,145.235 174.986,135.904 175.942,126.2 174.986,116.496 172.156,107.164 167.559,98.565 161.373,91.027 153.835,84.841 145.235,80.244 135.904,77.414 131.539,76.984 ccw(c131.324,77.617) 131.988,77.534 ccw(c131.707,77.815) 131.426,78.095 ccw(c131.145,77.815) 130.865,77.534 ccw(c131.152,77.261) 131.423,76.972
GND on GND (split plane): 81.099,142.197 81.755,141.928 81.659,141.693 81.002,141.962
GND on GND (split plane): 80.443,142.466 81.099,142.197 81.002,141.962 80.346,142.231
GND on GND (split plane): 80.512,141.102 80.933,142.128 81.168,142.031 80.747,141.005
GND on GND (split plane): 80.933,142.128 81.354,143.154 81.589,143.057 81.168,142.031
GND on GND (split plane): 82.894,105.532 83.547,105.807 83.646,105.573 82.993,105.298
GND on GND (split plane): 82.241,105.256 82.894,105.532 82.993,105.298 82.339,105.022
GND on GND (split plane): 83.06,105.464 83.492,104.442 83.258,104.344 82.826,105.365
GND on GND (split plane): 82.629,106.486 83.06,105.464 82.826,105.365 82.395,106.387
GND on GND (split plane): 99.122,155.977 99.9,156.733 100.077,156.55 99.3,155.795
GND on GND (split plane): 98.345,155.221 99.122,155.977 99.3,155.795 98.522,155.039
GND on GND (split plane): 99.302,155.974 100.058,155.197 99.876,155.02 99.12,155.797
GND on GND (split plane): 98.546,156.751 99.302,155.974 99.12,155.797 98.364,156.574
GND on GND (split plane): 105.583,169.507 105.858,168.853 105.624,168.755 105.349,169.409
GND on GND (split plane): 105.308,170.161 105.583,169.507 105.349,169.409 105.074,170.062
GND on GND (split plane): 104.394,169.145 105.417,169.575 105.515,169.341 104.493,168.911
GND on GND (split plane): 105.417,169.575 106.439,170.004 106.538,169.77 105.515,169.341
GND on GND (split plane): 110.241,80.944 110.51,81.6 110.745,81.504 110.476,80.848
GND on GND (split plane): 109.972,80.288 110.241,80.944 110.476,80.848 110.207,80.192
GND on GND (split plane): 110.407,81.014 111.433,80.593 111.337,80.358 110.311,80.779
GND on GND (split plane): 109.381,81.434 110.407,81.014 110.311,80.779 109.285,81.199
GND on GND (split plane): 121.035,79.731 121.894,79.731 121.894,79.477 121.035,79.477
GND on GND (split plane): 121.894,79.731 122.753,79.731 122.753,79.477 121.894,79.477
GND on GND (split plane): 121.767,79.604 121.767,80.763 122.021,80.763 122.021,79.604
GND on GND (split plane): 122.021,79.604 122.021,78.445 121.767,78.445 121.767,79.604
GND on GND (split plane): 121.035,83.931 121.894,83.931 121.894,83.677 121.035,83.677
GND on GND (split plane): 121.894,83.931 122.753,83.931 122.753,83.677 121.894,83.677
GND on GND (split plane): 121.767,83.804 121.767,85.063 122.021,85.063 122.021,83.804
GND on GND (split plane): 122.021,83.804 122.021,82.545 121.767,82.545 121.767,83.804
GND on GND (split plane): 129.685,83.931 130.544,83.931 130.544,83.677 129.685,83.677
GND on GND (split plane): 130.544,83.931 131.403,83.931 131.403,83.677 130.544,83.677
GND on GND (split plane): 130.417,83.804 130.417,85.063 130.671,85.063 130.671,83.804
GND on GND (split plane): 130.671,83.804 130.671,82.545 130.417,82.545 130.417,83.804
GND on GND (split plane): 129.685,79.731 130.544,79.731 130.544,79.477 129.685,79.477
GND on GND (split plane): 130.544,79.731 131.403,79.731 131.403,79.477 130.544,79.477
GND on GND (split plane): 130.417,79.604 130.417,80.763 130.671,80.763 130.671,79.604
GND on GND (split plane): 130.671,79.604 130.671,78.445 130.417,78.445 130.417,79.604
GND on GND (split plane): 141.65,170.866 141.924,171.521 142.158,171.423 141.884,170.768
GND on GND (split plane): 141.924,171.521 142.197,172.175 142.432,172.077 142.158,171.423
GND on GND (split plane): 141.067,172.017 142.09,171.589 141.992,171.354 140.969,171.782
GND on GND (split plane): 142.09,171.589 143.113,171.161 143.015,170.927 141.992,171.354
GND on GND (split plane): 146.798,83.573 147.069,82.918 146.834,82.821 146.563,83.476
GND on GND (split plane): 147.069,82.918 147.341,82.263 147.106,82.166 146.834,82.821
GND on GND (split plane): 146.903,82.987 147.928,83.412 148.025,83.177 147,82.752
GND on GND (split plane): 145.879,82.562 146.903,82.987 147,82.752 145.976,82.328
GND on GND (split plane): 168.704,146.745 169.359,147.015 169.456,146.78 168.8,146.51
GND on GND (split plane): 169.359,147.015 170.015,147.285 170.112,147.05 169.456,146.78
GND on GND (split plane): 169.103,147.971 169.525,146.946 169.29,146.849 168.868,147.875
GND on GND (split plane): 169.525,146.946 169.947,145.921 169.713,145.824 169.29,146.849
GND on GND (split plane): 170.909,110.761 171.564,110.49 171.467,110.255 170.812,110.527
GND on GND (split plane): 171.564,110.49 172.219,110.218 172.122,109.984 171.467,110.255
GND on GND (split plane): 171.398,110.421 171.823,111.446 172.058,111.349 171.633,110.324
GND on GND (split plane): 170.973,109.397 171.398,110.421 171.633,110.324 171.208,109.299
VCC on VCC (split plane): 95.481,152.435 96.258,153.191 96.435,153.009 95.658,152.253
VCC on VCC (split plane): 94.704,151.679 95.481,152.435 95.658,152.253 94.881,151.497
VCC on VCC (split plane): 95.66,152.432 96.416,151.655 96.234,151.478 95.478,152.255
VCC on VCC (split plane): 94.905,153.209 95.66,152.432 95.478,152.255 94.722,153.032

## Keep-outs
Board Outline Layer:
  lines w0.1 net "": 76.2,126.2 77.161,135.954 80.006,145.334 84.627,153.978 90.845,161.555 98.421,167.773 107.066,172.394 116.445,175.239 126.2,176.2 135.954,175.239 145.334,172.394 153.978,167.773 161.555,161.555 167.773,153.978 172.394,145.334 175.239,135.954 176.2,126.2 175.239,116.445 172.394,107.066 167.773,98.421 161.555,90.845 153.978,84.627 145.334,80.006 135.954,77.161 126.2,76.2 116.445,77.161 107.066,80.006 98.421,84.627 90.845,90.845 84.627,98.421 80.006,107.066 77.161,116.445 76.2,126.2
Multi-Layer:
  region net "": 160.219,126.175 ccw(c126.219,126.175) 92.219,126.175 ccw(c126.219,126.175)

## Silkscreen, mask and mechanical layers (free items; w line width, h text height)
Top Silkscreen Layer:
  lines w0.1 net "": 78.066,113.839 83.424,100.905 96.358,106.262 91.001,119.197 78.066,113.839 ; 78.066,138.561 83.424,151.495 96.358,146.137 91.001,133.203 78.066,138.561 ; 100.905,83.424 113.839,78.066 119.197,91.001 106.262,96.358 100.905,83.424 ; 100.905,168.976 113.839,174.333 119.197,161.399 106.262,156.042 100.905,168.976 ; 133.203,91.001 146.137,96.358 151.495,83.424 138.561,78.066 133.203,91.001 ; 133.203,161.399 146.137,156.042 151.495,168.976 138.561,174.333 133.203,161.399 ; 156.042,106.262 161.399,119.197 174.333,113.839 168.976,100.905 156.042,106.262 ; 156.042,146.137 161.399,133.203 174.333,138.561 168.976,151.495 156.042,146.137
  text "Circuller" at 154.854,161.377 h1.95 r315
  text "TM" at 164.695,154.051 h0.84 r315
  text "MPAM  /  Laboratory" at 89.008,148.769 h2.21 r46.71
  text "FDS" at 88.107,124.516 h1.69 r90.72
  text "@nonefffds" at 90.445,120.878 h1.3 r90.72
  text "https://MPAM-Lab.xyz" at 163.192,101.811 h0.97 r229.64
  text "Rev 1.2" at 104.645,95.118 h1.95 r135
Bottom Silkscreen Layer:
  text "Made for Rhythm Gamers" at 138.866,169.029 h1.3 r359.63
Mechanical Layer:
  circle w0.025 net "": c126.219,126.175 r34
